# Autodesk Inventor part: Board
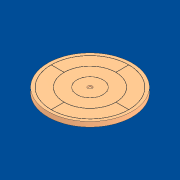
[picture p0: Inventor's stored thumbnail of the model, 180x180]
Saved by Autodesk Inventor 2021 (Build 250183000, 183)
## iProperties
Created: 2020-10
Part Number: Board
Material: Generic
Document SubType Name: Modeling
Designer: Stu
Density: 1 g/cm^3
Appearance: Default
Author: Stu
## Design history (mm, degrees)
sketch "Sketch1"
  geometry: C1 r 330.2 at (0, 0); 1 further point
  constraints: 1 centre point, 1 coincident
  dimensions: "d0" = 660.4 diameter of C1
extrude "Extrusion1" new body sketch "Sketch1" distance "d1" = 38.1; taper "d2" = 0 deg
sketch "Sketch3"
  geometry: C1 r 17.463 at (0, 0); 1 further point
  constraints: 1 centre point, 1 coincident
  dimensions: "d3" = 34.925 diameter of C1
extrude "Extrusion2" cut sketch "Sketch3" distance "d4" = 12.7; taper "d5" = 0 deg
sketch "Sketch4" dims "d7" = 406.4, "d8" = 609.6
  geometry: L1 (-203.2, 0)-(-304.8, 0); L2 (-203.949, -0.75)-(-304.049, -0.75); L3 (-304.049, 0.75)-(-203.949, 0.75); L4 (-462.28, 0)-(462.28, 0) reference; L5 (-0.75, -304.049)-(-0.75, -203.949); L6 (0, -203.2)-(0, -304.8); L7 (0.75, -203.949)-(0.75, -304.049); L8 (304.049, -0.75)-(203.949, -0.75); L9 (203.2, 0)-(304.8, 0); L10 (203.949, 0.75)-(304.049, 0.75); L11 (0.75, 304.049)-(0.75, 203.949); L12 (0, 203.2)-(0, 304.8); L13 (-0.75, 203.949)-(-0.75, 304.049); C1 r 101.6 at (0, 0); C2 r 101.225 at (0, 0); C3 r 101.975 at (0, 0); C4 r 202.45 at (0, 0); C5 r 305.55 at (0, 0); A1 r 203.95 centre (0, 0) between (-203.949, -0.75) and (-0.75, -203.949); A2 r 304.05 centre (0, 0) between (-304.049, -0.75) and (-0.75, -304.049); A3 r 203.95 centre (0, 0) between (0.75, -203.949) and (203.949, -0.75); A4 r 304.05 centre (0, 0) between (0.75, -304.049) and (304.049, -0.75); A5 r 203.95 centre (0, 0) between (203.949, 0.75) and (0.75, 203.949); A6 r 203.95 centre (0, 0) between (-0.75, 203.949) and (-203.949, 0.75); A7 r 304.05 centre (0, 0) between (304.049, 0.75) and (0.75, 304.049); A8 r 304.05 centre (0, 0) between (-0.75, 304.049) and (-304.049, 0.75); 3 further points
  constraints: 24 end point, 16 point on circle, 13 centre point, 9 coincident, 2 horizontal, 2 horizontal alignment, 1 collinear, 41 other
  dimensions: "d6" = 203.2 diameter of C1; "d9" = 202.45 diameter of C2; "d10" = 203.95 diameter of C3; "d11" = 0.75 dimension on C4; "d13" = 0.75 dimension on C5; "d15" = 0.75 distance between parallel lines of L1 L3; "d16" = 0.75 distance between parallel lines of L1 L2 (= d15); "d19" = 360 deg dimension on L3.start point (0, 0) L1.start (derived)
extrude "Extrusion3" cut sketch "Sketch4" distance "d21" = 0.75; taper "d22" = 0 deg
sketch "Sketch5" dims "d23" = 203.2
  geometry: L1 (-93.866, 38.881)-(0, 0); L2 (0, 0)-(0, 101.225); C1 r 3.175 at (-93.866, 38.881); C2 r 3.175 at (-93.866, -38.881); C3 r 3.175 at (-38.881, -93.866); C4 r 3.175 at (38.881, -93.866); C5 r 3.175 at (93.866, -38.881); C6 r 3.175 at (93.866, 38.881); C7 r 3.175 at (38.881, 93.866); C8 r 3.175 at (-38.881, 93.866); 3 further points
  constraints: 8 centre point, 4 end point, 1 coincident, 1 vertical, 1 vertical alignment, 21 other
  dimensions: "d24" = 6.35 diameter of C1; "d25" = 67.5 deg angle of L2 L1; "d28" = 360 deg dimension on point (0, 0) L1.start (derived)
extrude "Extrusion4" cut sketch "Sketch5" distance "d30" = 12.7; taper "d31" = 0 deg
sketch "Sketch6"
  geometry: C1 r 12.7 at (0, 0); 1 further point
  constraints: 1 centre point, 1 coincident
  dimensions: "d32" = 25.4 diameter of C1
extrude "Extrusion5" join sketch "Sketch6" distance "d33" = 6.35; taper "d34" = 0 deg
body "Solid1"
other parameters: "d12" = 0.75, "d14" = 0.75
